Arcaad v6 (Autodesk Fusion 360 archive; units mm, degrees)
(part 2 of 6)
sketch "Sketch14" plane through (0, -337.8868, -90.9298) normal (0, 0.9656, 0.2599) x axis (1, 0, 0)
  line L1 (212, -233.7285) -> (224, -233.7285)
  line L2 (212, -143.475) -> (212, -233.7285)
  line L3 (-288, -143.475) -> (212, -143.475)
  line L4 (-288, -233.7285) -> (-288, -143.475)
  line L5 (-300, -233.7285) -> (-288, -233.7285)
  line L6 (-300, -293.7285) -> (-300, -233.7285)
  line L7 (-288, -293.7285) -> (-300, -293.7285)
  line L8 (-288, -383.9821) -> (-288, -293.7285)
  line L9 (212, -383.9821) -> (-288, -383.9821)
  line L10 (212, -293.7285) -> (212, -383.9821)
  line L11 (224, -293.7285) -> (212, -293.7285)
  line L12 (224, -233.7285) -> (224, -293.7285)
  line L13 (212, -143.475) -> (-288, -143.475)
  line L14 (212, -383.9821) -> (212, -143.475)
  line L15 (-288, -383.9821) -> (212, -383.9821)
  line L16 (-288, -143.475) -> (-288, -383.9821)
  line L17 (212, -263.7285) -> (-288, -263.7285)
  line L18 (-38, -383.9821) -> (-38, -143.475)
  line L19 (87, -383.9821) -> (87, -143.475)
  line L20 (-163, -143.475) -> (-163, -383.9821)
  point P11 (212, -383.9821)
  point P16 (212, -383.9821)
  point P5 (-288, -143.475)
  point P14 (-288, -143.475)
  point P18 (-288, -263.7285)
  point P19 (212, -263.7285)
  point P20 (-38, -143.475)
  point P21 (-38, -383.9821)
  horizontal L13
  vertical L14
  horizontal L15
  vertical L16
  coincident P11 P16
  coincident P5 P14
  midpoint L16 P18
  midpoint L14 P19
  midpoint L3 P20
  midpoint L9 P21
  dimension "d74" distance P18 P19 = 500
  dimension "d75" = 125 (= "( 500 / 4 ) * 1 mm")
  dimension "d76" = 125 (= "( 500 / 4 ) * 1 mm")
component_insert "Component Insert3"
joint "Assemble1" OffsetX 0 OffsetY 0 OffsetZ 0 AngleZ 0 alignAngle 0 alignOffsetX 0 alignOffsetY 0 alignOffsetZ 0
work_plane "WorkPlane1"
form "Form1"
position "Position10"
mirror_component "MirrorComponent1"
derived_instance "DerivedInstance1"
derived_instance "DerivedInstance1"
derived_instance "DerivedInstance2"
derived_instance "DerivedInstance3"
derived_instance "DerivedInstance4"
derived_instance "DerivedInstance5"
derived_instance "DerivedInstance1"
derived_instance "DerivedInstance2"
derived_instance "DerivedInstance3"
position "Position11"
combine "Combine2"
position "Position12"
sketch "Sketch15" plane through (1060.5317, -231.9707, -369.061) normal (0, 0.9656, 0.2599) x axis (1, 0, 0)
  line L1 (-848.5317, -529.8285) -> (-836.5317, -529.8285)
  line L2 (-848.5317, -439.5749) -> (-848.5317, -529.8285)
  line L3 (-1348.5317, -439.5749) -> (-848.5317, -439.5749)
  line L4 (-1348.5317, -529.8285) -> (-1348.5317, -439.5749)
  line L5 (-1360.5317, -529.8285) -> (-1348.5317, -529.8285)
  line L6 (-1360.5317, -589.8285) -> (-1360.5317, -529.8285)
  line L7 (-1348.5317, -589.8285) -> (-1360.5317, -589.8285)
  line L8 (-1348.5317, -680.0821) -> (-1348.5317, -589.8285)
  line L9 (-848.5317, -680.0821) -> (-1348.5317, -680.0821)
  line L10 (-848.5317, -589.8285) -> (-848.5317, -680.0821)
  line L11 (-836.5317, -589.8285) -> (-848.5317, -589.8285)
  line L12 (-836.5317, -529.8285) -> (-836.5317, -589.8285)
  line L13 (-1207.5033, -539.8501) -> (-1239.5601, -539.8501)
  line L14 (-1207.5033, -579.8069) -> (-1207.5033, -539.8501)
  line L15 (-1239.5601, -579.8069) -> (-1207.5033, -579.8069)
  line L16 (-1239.5601, -539.8501) -> (-1239.5601, -579.8069)
  line L17 (-989.5601, -539.8501) -> (-957.5033, -539.8501)
  line L18 (-989.5601, -579.8069) -> (-989.5601, -539.8501)
  line L19 (-957.5033, -579.8069) -> (-989.5601, -579.8069)
  line L20 (-957.5033, -539.8501) -> (-957.5033, -579.8069)
  horizontal L13
  vertical L14
  horizontal L15
  vertical L16
  horizontal L17
  vertical L18
  horizontal L19
  vertical L20
extrude "Extrude2" cut sketch "Sketch15" profile of L13 L14 L15 L16 L17 L18 L19 L20 against normal blind 12
position "Position14"
sketch "Sketch16" plane through (0, 0, 0) normal (0, 1, 0) x axis (1, 0, 0)
  line L1 (2740, 0) -> (300, 0)
  line L2 (2740, -1220) -> (2740, 0)
  line L3 (300, -1220) -> (2740, -1220)
  line L4 (300, 0) -> (300, -1220)
  point P2 (300, 0)
  point P3 (2740, 0)
  point P5 (300, -1220)
  horizontal L1
  vertical L2
  horizontal L3
  vertical L4
  dimension "d91" distance P2 P3 = 2440
  dimension "d92" distance P2 P5 = 1220
extrude "Extrude1" new body sketch "Sketch16" against normal blind 12
sketch "Sketch18" plane through (-288, 0, 0) normal (1, 0, 0) x axis (0, 0, -1)
  line L1 (-133.2097, -404.4191) -> (-134.7689, -398.6252)
  line L2 (-123.5532, -401.8204) -> (-133.2097, -404.4191)
  line L3 (-121.994, -407.6143) -> (-123.5532, -401.8204)
  line L4 (-199.2455, -428.4037) -> (-121.994, -407.6143)
  line L5 (-200.8048, -422.6098) -> (-199.2455, -428.4037)
  line L6 (-191.1483, -420.0112) -> (-200.8048, -422.6098)
  line L7 (-192.7075, -414.2173) -> (-191.1483, -420.0112)
  line L8 (-134.7689, -398.6252) -> (-192.7075, -414.2173)
  line L9 (-208.6564, -584.2019) -> (-287.6564, -584.2019)
  line L10 (-208.6564, -596.2019) -> (-208.6564, -584.2019)
  line L11 (-128.6564, -596.2019) -> (-208.6564, -596.2019)
  line L12 (-128.6564, -584.2019) -> (-128.6564, -596.2019)
  line L13 (-33.6564, -584.2019) -> (-128.6564, -584.2019)
  line L14 (-33.6564, -596.2019) -> (-33.6564, -584.2019)
  line L15 (46.3436, -596.2019) -> (-33.6564, -596.2019)
  line L16 (46.3436, -584.2019) -> (46.3436, -596.2019)
  line L17 (141.3436, -584.2019) -> (46.3436, -584.2019)
  line L18 (141.3436, -596.2019) -> (141.3436, -584.2019)
  line L19 (221.3436, -596.2019) -> (141.3436, -596.2019)
  line L20 (221.3436, -584.2019) -> (221.3436, -596.2019)
  line L21 (300.3436, -584.2019) -> (221.3436, -584.2019)
  line L22 (300.3436, -393.4667) -> (300.3436, -584.2019)
  line L23 (312.3436, -393.4667) -> (300.3436, -393.4667)
  line L24 (312.3436, -313.4667) -> (312.3436, -393.4667)
  line L25 (300.3436, -313.4667) -> (312.3436, -313.4667)
  line L26 (300.3436, -143.4667) -> (300.3436, -313.4667)
  line L27 (312.3436, -143.4667) -> (300.3436, -143.4667)
  line L28 (312.3436, -63.4667) -> (312.3436, -143.4667)
  line L29 (300.3436, -63.4667) -> (312.3436, -63.4667)
  line L30 (300.3436, 106.5333) -> (300.3436, -63.4667)
  line L31 (312.3436, 106.5333) -> (300.3436, 106.5333)
  line L32 (312.3436, 186.5333) -> (312.3436, 106.5333)
  line L33 (300.3436, 186.5333) -> (312.3436, 186.5333)
  line L34 (300.3436, 377.2686) -> (300.3436, 186.5333)
  line L35 (207.9218, 377.2686) -> (300.3436, 377.2686)
  line L36 (207.9218, 389.2686) -> (207.9218, 377.2686)
  line L37 (127.9218, 389.2686) -> (207.9218, 389.2686)
  line L38 (127.9218, 377.2686) -> (127.9218, 389.2686)
  line L39 (23.4999, 377.2686) -> (127.9218, 377.2686)
  line L40 (23.4999, 389.2686) -> (23.4999, 377.2686)
  line L41 (11.6822, 391.3524) -> (23.4999, 389.2686)
  line L42 (2.9998, 342.112) -> (11.6822, 391.3524)
  line L43 (64.0579, 331.3458) -> (2.9998, 342.112)
  line L44 (66.1417, 343.1635) -> (64.0579, 331.3458)
  line L45 (77.9594, 341.0797) -> (66.1417, 343.1635)
  line L46 (60.5946, 242.5989) -> (77.9594, 341.0797)
  line L47 (48.7769, 244.6827) -> (60.5946, 242.5989)
  line L48 (31.412, 146.2019) -> (48.7769, 244.6827)
  line L49 (43.2297, 144.1182) -> (31.412, 146.2019)
  line L50 (25.8649, 45.6374) -> (43.2297, 144.1182)
  line L51 (14.0472, 47.7212) -> (25.8649, 45.6374)
  line L52 (1.0236, -26.1394) -> (14.0472, 47.7212)
  line L53 (12.8413, -28.2232) -> (1.0236, -26.1394)
  line L54 (-13.2059, -175.9444) -> (12.8413, -28.2232)
  line L55 (-25.0236, -173.8606) -> (-13.2059, -175.9444)
  line L56 (-33.706, -223.101) -> (-25.0236, -173.8606)
  line L57 (-21.8883, -225.1847) -> (-33.706, -223.101)
  line L58 (-43.5944, -348.2857) -> (-21.8883, -225.1847)
  line L59 (-55.412, -346.2019) -> (-43.5944, -348.2857)
  line L60 (-142.5649, -369.6559) -> (-55.412, -346.2019)
  line L61 (-141.0057, -375.4498) -> (-142.5649, -369.6559)
  line L62 (-131.3492, -372.8511) -> (-141.0057, -375.4498)
  line L63 (-129.79, -378.645) -> (-131.3492, -372.8511)
  line L64 (-207.0416, -399.4344) -> (-129.79, -378.645)
  line L65 (-208.6008, -393.6405) -> (-207.0416, -399.4344)
  line L66 (-198.9443, -391.0418) -> (-208.6008, -393.6405)
  line L67 (-200.5035, -385.248) -> (-198.9443, -391.0418)
  line L68 (-287.6564, -408.7019) -> (-200.5035, -385.248)
  line L69 (-287.6564, -477.4519) -> (-287.6564, -408.7019)
  line L70 (-299.6564, -477.4519) -> (-287.6564, -477.4519)
  line L71 (-299.6564, -527.4519) -> (-299.6564, -477.4519)
  line L72 (-287.6564, -527.4519) -> (-299.6564, -527.4519)
  line L73 (-287.6564, -584.2019) -> (-287.6564, -527.4519)
  line L74 (240, -320) -> (-30, -320)
  line L75 (240, -332) -> (240, -320)
  line L76 (-30, -332) -> (240, -332)
  line L77 (-30, -320) -> (-30, -332)
  line L78 (105, -332) -> (105, -320)
  line L79 (240, -326) -> (-30, -326)
  line L80 (37.5, -332) -> (37.5, -320)
  line L81 (172.5, -332) -> (172.5, -320)
  line L82 (17.5, -320) -> (37.5, -320)
  line L83 (17.5, -332) -> (17.5, -320)
  line L84 (37.5, -332) -> (17.5, -332)
  line L85 (37.5, -320) -> (37.5, -332)
  line L86 (57.5, -320) -> (37.5, -320)
  line L87 (57.5, -332) -> (57.5, -320)
  line L88 (37.5, -332) -> (57.5, -332)
  line L89 (37.5, -320) -> (37.5, -332)
  line L90 (67.5, -320) -> (37.5, -320)
  line L91 (67.5, -332) -> (67.5, -320)
  line L92 (37.5, -332) -> (67.5, -332)
  line L93 (37.5, -320) -> (37.5, -332)
  line L94 (7.5, -320) -> (37.5, -320)
  line L95 (7.5, -332) -> (7.5, -320)
  line L96 (37.5, -332) -> (7.5, -332)
  line L97 (37.5, -320) -> (37.5, -332)
  line L98 (202.5, -332) -> (202.5, -320)
  line L99 (172.5, -332) -> (202.5, -332)
  line L100 (202.5, -320) -> (172.5, -320)
  line L101 (172.5, -320) -> (172.5, -332)
  line L102 (152.5, -332) -> (152.5, -320)
  line L103 (192.5, -332) -> (192.5, -320)
  line L104 (172.5, -320) -> (172.5, -332)
  line L105 (172.5, -332) -> (142.5, -332)
  line L106 (142.5, -320) -> (172.5, -320)
  line L107 (142.5, -332) -> (142.5, -320)
  point P79 (105, -320)
  point P80 (105, -332)
  point P81 (-30, -326)
  point P82 (240, -326)
  point P91 (57.5, -332)
  point P83 (37.5, -320)
  point P102 (172.5, -320)
  point P87 (17.5, -320)
  point P105 (192.5, -320)
  point P88 (17.5, -332)
  point P106 (192.5, -332)
  point P90 (57.5, -320)
  point P103 (152.5, -320)
  point P104 (152.5, -332)
  point P93 (67.5, -320)
  point P109 (142.5, -320)
  point P94 (67.5, -332)
  point P108 (142.5, -332)
  point P95 (37.5, -332)
  point P107 (172.5, -332)
  point P96 (7.5, -320)
  point P99 (202.5, -320)
  point P97 (7.5, -332)
  point P100 (202.5, -332)
  point P98 (37.5, -332)
  point P101 (172.5, -332)
  point P76 (240, -320)
  point P77 (240, -332)
  point P78 (-30, -332)
  horizontal L74
  vertical L75
  horizontal L76
  vertical L77
  midpoint L74 P79
  midpoint L76 P80
  midpoint L77 P81
  midpoint L75 P82
  horizontal L82
  vertical L83
  horizontal L84
  vertical L85
  horizontal L86
  vertical L87
  horizontal L88
  vertical L89
  coincident L76 P91
  horizontal L90
  vertical L91
  horizontal L92
  vertical L93
  horizontal L94
  vertical L95
  horizontal L96
  vertical L97
  symmetric L78 P83 P102
  symmetric L78 P87 P105
  symmetric L78 P88 P106
  symmetric L78 P90 P103
  symmetric L78 P91 P104
  symmetric L78 P93 P109
  symmetric L78 P94 P108
  symmetric L78 P95 P107
  symmetric L78 P96 P99
  symmetric L78 P97 P100
  symmetric L78 P98 P101
  dimension "d240" distance P76 P77 = 12
  dimension "d241" distance P77 P78 = 270
  dimension "d242" = 67.5 (= "( 270 / 4 ) * 1 mm")
  dimension "d243" = 67.5 (= "( 270 / 4 ) * 1 mm")
  dimension "d244" distance P83 P87 = 20
  dimension "d245" distance P83 P90 = 20
  dimension "d246" distance P83 P93 = 30
  dimension "d247" distance P83 P96 = 30
extrude "Extrude1" new body sketch "Sketch18" profile of L74 L75 L76 L77 L78 L79 L80 L81 L82 L83 L84 L85 L86 L87 L88 L89 L90 L91 L92 L93 L94 L95 L96 L97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 to an object
extrude "Extrude2" add sketch "Sketch18" profile of L74 L76 L79 L80 L81 L82 L83 L84 L85 L86 L87 L88 L89 L90 L91 L92 L93 L94 L95 L96 L97 L98 L99 L100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 to an object
work_plane "WorkPlane3" sketch "Sketch18"
mirror_component "MirrorComponent3"
derived_instance "DerivedInstance3"
combine "Combine1"
combine "Combine3"
combine "Combine3"
joint "Assemble2" alignAngle 0 alignOffsetX -925 alignOffsetY 275 alignOffsetZ 0
joint "Assemble3" alignAngle 0 alignOffsetX -375 alignOffsetY 100 alignOffsetZ 0
joint "Assemble4" alignAngle 0 alignOffsetX -925 alignOffsetY -175 alignOffsetZ 0
joint "Assemble5" alignAngle 0 alignOffsetX -925 alignOffsetY -450 alignOffsetZ 0
joint "Assemble6" alignAngle 0 alignOffsetX -350 alignOffsetY -500 alignOffsetZ -12
component_from_bodies "Body->Comp1"
ground "Ground1"
position "Position15"
work_plane "WorkPlane2" AlongDistance 400
mirror_component "MirrorComponent2"
derived_instance "DerivedInstance2"
joint "Assemble7" alignAngle 15 alignOffsetX 600 alignOffsetY -400 alignOffsetZ -12
joint "Assemble8" alignAngle 270 alignOffsetX -50 alignOffsetY -575 alignOffsetZ -12
position "Position16"
joint "Assemble9" alignAngle -90 alignOffsetX 450 alignOffsetY 200 alignOffsetZ 0
ground "Ground2"
ground "Ground3"
joint "Assemble10" alignAngle 0 alignOffsetX 575 alignOffsetY -275 alignOffsetZ 0
position "Position17"
sketch "Sketch17" plane through (0, 0, 0) normal (0, 1, 0) x axis (1, 0, 0)
  line L1 (2740, -1300) -> (300, -1300)
  line L2 (2740, -2520) -> (2740, -1300)
  line L3 (300, -2520) -> (2740, -2520)
  line L4 (300, -1300) -> (300, -2520)
  point P2 (300, -1300)
  point P3 (2740, -1300)
  point P5 (300, -2520)
  horizontal L1
  vertical L2
  horizontal L3
  vertical L4
  dimension "d204" distance P2 P3 = 2440
  dimension "d205" distance P2 P5 = 1220
extrude "Extrude2" new body sketch "Sketch17" against normal blind 12
component_from_bodies "Body->Comp2"
ground "Ground4"
joint "Assemble11" alignAngle 0 alignOffsetX -950 alignOffsetY 450 alignOffsetZ 0
joint "Assemble12" alignAngle 0 alignOffsetX -950 alignOffsetY 200 alignOffsetZ -12
position "Position18"
joint "Assemble13" alignAngle 0 alignOffsetX -950 alignOffsetY -50 alignOffsetZ 0
sketch "Sketch19" plane through (0, 0, 0) normal (0, 1, 0) x axis (-1, 0, 0)
  line L1 (-2740, 2520) -> (-300, 2520)
  line L2 (-2740, 1300) -> (-2740, 2520)
  line L3 (-300, 1300) -> (-2740, 1300)
  line L4 (-300, 2520) -> (-300, 1300)
  line L5 (-2610.2394, 933.8303) -> (-2610.2459, 927.8302)
  line L6 (-2550.2394, 933.7651) -> (-2610.2394, 933.8303)
  line L7 (-2550.2459, 927.7651) -> (-2550.2394, 933.7651)
  line L8 (-2560.2459, 927.776) -> (-2550.2459, 927.7651)
  line L9 (-2560.2524, 921.776) -> (-2560.2459, 927.776)
  line L10 (-2600.2524, 921.8194) -> (-2560.2524, 921.776)
  line L11 (-2600.2459, 927.8194) -> (-2600.2524, 921.8194)
  line L12 (-2610.2459, 927.8302) -> (-2600.2459, 927.8194)
  line L13 (-2475.2394, 933.6837) -> (-2475.246, 927.6837)
  line L14 (-2415.2395, 933.6185) -> (-2475.2394, 933.6837)
  line L15 (-2415.246, 927.6185) -> (-2415.2395, 933.6185)
  line L16 (-2425.246, 927.6294) -> (-2415.246, 927.6185)
  line L17 (-2425.2525, 921.6294) -> (-2425.246, 927.6294)
  line L18 (-2465.2525, 921.6728) -> (-2425.2525, 921.6294)
  line L19 (-2465.246, 927.6728) -> (-2465.2525, 921.6728)
  line L20 (-2475.246, 927.6837) -> (-2465.246, 927.6728)
  line L21 (-2563.7962, 1197.9819) -> (-2563.8092, 1185.9819)
  line L22 (-2613.7961, 1198.0362) -> (-2563.7962, 1197.9819)
  line L23 (-2613.8092, 1186.0362) -> (-2613.7961, 1198.0362)
  line L24 (-2707.8091, 1186.1383) -> (-2613.8092, 1186.0362)
  line L25 (-2708.0325, 980.4031) -> (-2707.8091, 1186.1383)
  line L26 (-2720.0325, 980.4161) -> (-2708.0325, 980.4031)
  line L27 (-2720.0868, 930.4162) -> (-2720.0325, 980.4161)
  line L28 (-2708.0868, 930.4031) -> (-2720.0868, 930.4162)
  line L29 (-2708.3039, 730.4033) -> (-2708.0868, 930.4031)
  line L30 (-2720.3039, 730.4163) -> (-2708.3039, 730.4033)
  line L31 (-2720.3582, 680.4163) -> (-2720.3039, 730.4163)
  line L32 (-2708.3582, 680.4033) -> (-2720.3582, 680.4163)
  line L33 (-2708.5753, 480.4034) -> (-2708.3582, 680.4033)
  line L34 (-2720.5753, 480.4164) -> (-2708.5753, 480.4034)
  line L35 (-2720.6296, 430.4165) -> (-2720.5753, 480.4164)
  line L36 (-2708.6296, 430.4034) -> (-2720.6296, 430.4165)
  line L37 (-2708.8529, 224.6683) -> (-2708.6296, 430.4034)
  line L38 (-2601.4312, 224.5517) -> (-2708.8529, 224.6683)
  line L39 (-2601.4442, 212.5517) -> (-2601.4312, 224.5517)
  line L40 (-2551.4442, 212.4974) -> (-2601.4442, 212.5517)
  line L41 (-2551.4312, 224.4974) -> (-2551.4442, 212.4974)
  line L42 (-2432.0094, 224.3677) -> (-2551.4312, 224.4974)
  line L43 (-2432.0224, 212.3677) -> (-2432.0094, 224.3677)
  line L44 (-2420.207, 210.2711) -> (-2432.0224, 212.3677)
  line L45 (-2411.4712, 259.5021) -> (-2420.207, 210.2711)
  line L46 (-2472.5175, 270.3345) -> (-2411.4712, 259.5021)
  line L47 (-2474.6141, 258.5191) -> (-2472.5175, 270.3345)
  line L48 (-2486.4295, 260.6157) -> (-2474.6141, 258.5191)
  line L49 (-2464.5899, 383.6931) -> (-2486.4295, 260.6157)
  line L50 (-2452.7745, 381.5964) -> (-2464.5899, 383.6931)
  line L51 (-2444.0386, 430.8274) -> (-2452.7745, 381.5964)
  line L52 (-2455.854, 432.924) -> (-2444.0386, 430.8274)
  line L53 (-2429.6464, 580.6168) -> (-2455.854, 432.924)
  line L54 (-2417.831, 578.5202) -> (-2429.6464, 580.6168)
  line L55 (-2409.0952, 627.7511) -> (-2417.831, 578.5202)
  line L56 (-2420.9106, 629.8477) -> (-2409.0952, 627.7511)
  line L57 (-2394.703, 777.5405) -> (-2420.9106, 629.8477)
  line L58 (-2382.8876, 775.4439) -> (-2394.703, 777.5405)
  line L59 (-2374.1517, 824.6748) -> (-2382.8876, 775.4439)
  line L60 (-2385.9671, 826.7714) -> (-2374.1517, 824.6748)
  line L61 (-2364.1275, 949.8488) -> (-2385.9671, 826.7714)
  line L62 (-2352.3121, 947.7522) -> (-2364.1275, 949.8488)
  line L63 (-2265.1338, 971.1115) -> (-2352.3121, 947.7522)
  line L64 (-2266.6867, 976.9071) -> (-2265.1338, 971.1115)
  line L65 (-2276.346, 974.3189) -> (-2266.6867, 976.9071)
  line L66 (-2277.8989, 980.1144) -> (-2276.346, 974.3189)
  line L67 (-2200.6248, 1000.82) -> (-2277.8989, 980.1144)
  line L68 (-2199.0719, 995.0244) -> (-2200.6248, 1000.82)
  line L69 (-2208.7312, 992.4362) -> (-2199.0719, 995.0244)
  line L70 (-2207.1783, 986.6407) -> (-2208.7312, 992.4362)
  line L71 (-2120, 1010) -> (-2207.1783, 986.6407)
  line L72 (-2119.9254, 1078.75) -> (-2120, 1010)
  line L73 (-2107.9254, 1078.7369) -> (-2119.9254, 1078.75)
  line L74 (-2107.8711, 1128.7369) -> (-2107.9254, 1078.7369)
  line L75 (-2119.8711, 1128.7499) -> (-2107.8711, 1128.7369)
  line L76 (-2119.8095, 1185.4999) -> (-2119.8711, 1128.7499)
  line L77 (-2213.8094, 1185.6019) -> (-2119.8095, 1185.4999)
  line L78 (-2213.7964, 1197.6019) -> (-2213.8094, 1185.6019)
  line L79 (-2263.7964, 1197.6562) -> (-2213.7964, 1197.6019)
  line L80 (-2263.8094, 1185.6562) -> (-2263.7964, 1197.6562)
  line L81 (-2388.8093, 1185.7919) -> (-2263.8094, 1185.6562)
  line L82 (-2388.7963, 1197.7919) -> (-2388.8093, 1185.7919)
  line L83 (-2438.7963, 1197.8462) -> (-2388.7963, 1197.7919)
  line L84 (-2438.8093, 1185.8462) -> (-2438.7963, 1197.8462)
  line L85 (-2563.8092, 1185.9819) -> (-2438.8093, 1185.8462)
  line L86 (-2284.1105, 1003.2967) -> (-2274.4513, 1005.8848)
  line L87 (-2285.6635, 1009.0922) -> (-2284.1105, 1003.2967)
  line L88 (-2208.3894, 1029.7977) -> (-2285.6635, 1009.0922)
  line L89 (-2206.8365, 1024.0022) -> (-2208.3894, 1029.7977)
  line L90 (-2216.4957, 1021.414) -> (-2206.8365, 1024.0022)
  line L91 (-2214.9428, 1015.6184) -> (-2216.4957, 1021.414)
  line L92 (-2272.8984, 1000.0893) -> (-2214.9428, 1015.6184)
  line L93 (-2274.4513, 1005.8848) -> (-2272.8984, 1000.0893)
  line L94 (-1970, 650) -> (-2190, 650)
  line L95 (-1970, 170) -> (-1970, 650)
  line L96 (-2190, 170) -> (-1970, 170)
  line L97 (-2190, 650) -> (-2190, 170)
  line L98 (-1980, 747.9677) -> (-1900, 747.9677)
  line L99 (-1980, 753.9677) -> (-1980, 747.9677)
  line L100 (-1965, 753.9677) -> (-1980, 753.9677)
  line L101 (-1965, 759.9677) -> (-1965, 753.9677)
  line L102 (-2055, 759.9677) -> (-1965, 759.9677)
  line L103 (-2055, 753.9677) -> (-2055, 759.9677)
  line L104 (-2040, 753.9677) -> (-2055, 753.9677)
  line L105 (-2040, 747.9677) -> (-2040, 753.9677)
  line L106 (-2120, 747.9677) -> (-2040, 747.9677)
  line L107 (-2120, 753.9677) -> (-2120, 747.9677)
  line L108 (-2105, 753.9677) -> (-2120, 753.9677)
  line L109 (-2105, 759.9677) -> (-2105, 753.9677)
  line L110 (-2195, 759.9677) -> (-2105, 759.9677)
  line L111 (-2195, 753.9677) -> (-2195, 759.9677)
  line L112 (-2180, 753.9677) -> (-2195, 753.9677)
  line L113 (-2180, 747.9677) -> (-2180, 753.9677)
  line L114 (-2260, 747.9677) -> (-2180, 747.9677)
  line L115 (-2260, 753.9677) -> (-2260, 747.9677)
  line L116 (-2245, 753.9677) -> (-2260, 753.9677)
  line L117 (-2245, 759.9677) -> (-2245, 753.9677)
  line L118 (-2342, 759.9677) -> (-2245, 759.9677)
  line L119 (-2342, 634.9677) -> (-2342, 759.9677)
  line L120 (-2336, 634.9677) -> (-2342, 634.9677)
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sketch "Sketch20" plane through (0, 0, 0) normal (0, 1, 0) x axis (-1, 0, 0)
  line L1 (-856.772, 135) -> (-851.228, 135)
  line L2 (-856.772, 29) -> (-856.772, 135)
  line L3 (-780, 29) -> (-856.772, 29)
  line L4 (-780.0022, 35) -> (-780, 29)
  line L5 (-795.0022, 35) -> (-780.0022, 35)
  line L6 (-795.0045, 41) -> (-795.0022, 35)
  line L7 (-715.0045, 41) -> (-795.0045, 41)
  line L8 (-715.0022, 35) -> (-715.0045, 41)
  line L9 (-730.0022, 35) -> (-715.0022, 35)
  line L10 (-730.0022, 29) -> (-730.0022, 35)
  line L11 (-620, 29) -> (-730.0022, 29)
  line L12 (-620, 35) -> (-620, 29)
  line L13 (-635.0022, 35) -> (-620, 35)
  line L14 (-635.0045, 41) -> (-635.0022, 35)
  line L15 (-555.0045, 41) -> (-635.0045, 41)
  line L16 (-555.0022, 35) -> (-555.0045, 41)
  line L17 (-570.0022, 35) -> (-555.0022, 35)
  line L18 (-570.0022, 29) -> (-570.0022, 35)
  line L19 (-460, 29) -> (-570.0022, 29)
  line L20 (-460, 35) -> (-460, 29)
  line L21 (-475.0022, 35) -> (-460, 35)
  line L22 (-475.0045, 41) -> (-475.0022, 35)
  line L23 (-395.0045, 41) -> (-475.0045, 41)
  line L24 (-395.0022, 35) -> (-395.0045, 41)
  line L25 (-410.0022, 35) -> (-395.0022, 35)
  line L26 (-410.0022, 29) -> (-410.0022, 35)
  line L27 (-333.228, 29) -> (-410.0022, 29)
  line L28 (-333.228, 135) -> (-333.228, 29)
  line L29 (-339.228, 135) -> (-333.228, 135)
  line L30 (-339.228, 120) -> (-339.228, 135)
  line L31 (-345.228, 120) -> (-339.228, 120)
  line L32 (-345.228, 200) -> (-345.228, 120)
  line L33 (-339.228, 200) -> (-345.228, 200)
  line L34 (-339.228, 185) -> (-339.228, 200)
  line L35 (-333.228, 185) -> (-339.228, 185)
  line L36 (-333.228, 310) -> (-333.228, 185)
  line L37 (-339.228, 310) -> (-333.228, 310)
  line L38 (-339.228, 295) -> (-339.228, 310)
  line L39 (-345.228, 295) -> (-339.228, 295)
  line L40 (-345.228, 375) -> (-345.228, 295)
  line L41 (-339.228, 375) -> (-345.228, 375)
  line L42 (-339.228, 360) -> (-339.228, 375)
  line L43 (-333.228, 360) -> (-339.228, 360)
  line L44 (-333.228, 485) -> (-333.228, 360)
  line L45 (-339.228, 485) -> (-333.228, 485)
  line L46 (-339.228, 470) -> (-339.228, 485)
  line L47 (-345.228, 470) -> (-339.228, 470)
  line L48 (-345.228, 550) -> (-345.228, 470)
  line L49 (-339.228, 550) -> (-345.228, 550)
  line L50 (-339.228, 535) -> (-339.228, 550)
  line L51 (-333.228, 535) -> (-339.228, 535)
  line L52 (-333.228, 641) -> (-333.228, 535)
  line L53 (-410.228, 641) -> (-333.228, 641)
  line L54 (-410.228, 635) -> (-410.228, 641)
  line L55 (-395.2258, 635) -> (-410.228, 635)
  line L56 (-395.2236, 629) -> (-395.2258, 635)
  line L57 (-475.2236, 629) -> (-395.2236, 629)
  line L58 (-475.2258, 635) -> (-475.2236, 629)
  line L59 (-460.2258, 635) -> (-475.2258, 635)
  line L60 (-460.2258, 641) -> (-460.2258, 635)
  line L61 (-570.228, 641) -> (-460.2258, 641)
  line L62 (-570.228, 640.9907) -> (-570.228, 641)
  line L63 (-570.2258, 635) -> (-570.228, 640.9907)
  line L64 (-555.2258, 635) -> (-570.2258, 635)
  line L65 (-555.2236, 629) -> (-555.2258, 635)
  line L66 (-635.2236, 629) -> (-555.2236, 629)
  line L67 (-635.2258, 635) -> (-635.2236, 629)
  line L68 (-620.2258, 635) -> (-635.2258, 635)
  line L69 (-620.228, 640.9907) -> (-620.2258, 635)
  line L70 (-620.228, 641) -> (-620.228, 640.9907)
  line L71 (-730.228, 641) -> (-620.228, 641)
  line L72 (-730.228, 635) -> (-730.228, 641)
  line L73 (-715.2258, 635) -> (-730.228, 635)
  line L74 (-715.2236, 629) -> (-715.2258, 635)
  line L75 (-795.2236, 629) -> (-715.2236, 629)
  line L76 (-795.2258, 635) -> (-795.2236, 629)
  line L77 (-780.2258, 635) -> (-795.2258, 635)
  line L78 (-780.2258, 641) -> (-780.2258, 635)
  line L79 (-856.772, 641) -> (-780.2258, 641)
  line L80 (-856.772, 535) -> (-856.772, 641)
  line L81 (-851.228, 535) -> (-856.772, 535)
  line L82 (-851.228, 550) -> (-851.228, 535)
  line L83 (-845.228, 550) -> (-851.228, 550)
  line L84 (-845.228, 470) -> (-845.228, 550)
  line L85 (-851.228, 470) -> (-845.228, 470)
  line L86 (-851.228, 485) -> (-851.228, 470)
  line L87 (-856.772, 485) -> (-851.228, 485)
  line L88 (-856.772, 360) -> (-856.772, 485)
  line L89 (-851.228, 360) -> (-856.772, 360)
  line L90 (-851.228, 375) -> (-851.228, 360)
  line L91 (-845.228, 375) -> (-851.228, 375)
  line L92 (-845.228, 295) -> (-845.228, 375)
  line L93 (-851.228, 295) -> (-845.228, 295)
  line L94 (-851.228, 310) -> (-851.228, 295)
  line L95 (-856.772, 310) -> (-851.228, 310)
  line L96 (-856.772, 185) -> (-856.772, 310)
  line L97 (-851.228, 185) -> (-856.772, 185)
  line L98 (-851.228, 200) -> (-851.228, 185)
  line L99 (-845.228, 200) -> (-851.228, 200)
  line L100 (-845.228, 120) -> (-845.228, 200)
  line L101 (-851.228, 120) -> (-845.228, 120)
  line L102 (-851.228, 135) -> (-851.228, 120)
  line L103 (-1104.9955, 990.7353) -> (-1104.9955, 1002.7353)
  line L104 (-1024.9955, 990.7353) -> (-1104.9955, 990.7353)
  line L105 (-1024.9955, 1002.7353) -> (-1024.9955, 990.7353)
  line L106 (-944.9955, 1002.7353) -> (-1024.9955, 1002.7353)
  line L107 (-944.9955, 990.7353) -> (-944.9955, 1002.7353)
  line L108 (-883, 990.7353) -> (-944.9955, 990.7353)
  line L109 (-883, 785) -> (-883, 990.7353)
  line L110 (-889, 785) -> (-883, 785)
  line L111 (-889, 800) -> (-889, 785)
  line L112 (-895, 800) -> (-889, 800)
  line L113 (-895, 720) -> (-895, 800)
  line L114 (-889, 720) -> (-895, 720)
  line L115 (-889, 735) -> (-889, 720)
  line L116 (-883, 735) -> (-889, 735)
  line L117 (-883, 535) -> (-883, 735)
  line L118 (-889, 535) -> (-883, 535)
  line L119 (-889, 550) -> (-889, 535)
  line L120 (-895, 550) -> (-889, 550)
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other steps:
derived_base_feature "Derived Base Feature1"
derived_base_feature "Derived Base Feature1"
derived_base_feature "Derived Base Feature1"
derived_base_feature "Derived Base Feature1"
derived_base_feature "Derived Base Feature1"
derived_base_feature "Derived Base Feature1"
derived_base_feature "Derived Base Feature1"
derived_base_feature "Derived Base Feature1"
derived_base_feature "Derived Base Feature1"
derived_base_feature "Derived Base Feature1"
create_component "CreateComponent1"
create_component "CreateComponent2"
create_component "CreateComponent3"
create_component "CreateComponent4"
create_component "CreateComponent5"
create_component "CreateComponent6"
create_component "CreateComponent7"
create_component "CreateComponent8"
create_component "CreateComponent9"
create_component "CreateComponent10"
joint_origin "JointOrigin1" sketch "Sketch14" OffsetX 0 OffsetY 0 OffsetZ 0 AngleZ 0
create_component "CreateComponent11"
create_component "CreateComponent12"
create_component "CreateComponent13"
create_component "CreateComponent14"
create_component "CreateComponent15"
create_component "CreateComponent16"
joint_origin "JointOrigin1" OffsetX 0 OffsetY 0 OffsetZ 0 AngleZ 0
joint_origin "JointOrigin2" OffsetX 0 OffsetY 0 OffsetZ 0 AngleZ 0
joint_origin "JointOrigin1" OffsetX 0 OffsetY 0 OffsetZ 0 AngleZ 0
joint_origin "JointOrigin3" OffsetX 0 OffsetY 0 OffsetZ 0 AngleZ 0
joint_origin "JointOrigin1" OffsetX 0 OffsetY 0 OffsetZ 0 AngleZ 0
joint_origin "JointOrigin4" OffsetX 0 OffsetY 0 OffsetZ 0 AngleZ 0
joint_origin "JointOrigin2" OffsetX 0 OffsetY 0 OffsetZ 0 AngleZ 0
joint_origin "JointOrigin5" OffsetX 0 OffsetY 0 OffsetZ 0 AngleZ 0
joint_origin "JointOrigin1" OffsetX 0 OffsetY 0 OffsetZ 0 AngleZ 0
joint_origin "JointOrigin6" OffsetX 0 OffsetY 0 OffsetZ 0 AngleZ 0
create_component "CreateComponent17"
base_feature "Base Feature1"
remove_body "RemoveBody1"
create_component "CreateComponent18"
derived_base_feature "Derived Base Feature1"
joint_origin "JointOrigin1" OffsetX 0 OffsetY 0 OffsetZ 0 AngleZ 0
joint_origin "JointOrigin1" OffsetX 0 OffsetY 0 OffsetZ 0 AngleZ 0
joint_origin "JointOrigin1" OffsetX 0 OffsetY 0 OffsetZ 0 AngleZ 0
joint_origin "JointOrigin2" OffsetX 0 OffsetY 0 OffsetZ 0 AngleZ 0
joint_origin "JointOrigin1" OffsetX 0 OffsetY 0 OffsetZ 0 AngleZ 0
joint_origin "JointOrigin3" OffsetX 0 OffsetY 0 OffsetZ 0 AngleZ 0
joint_origin "JointOrigin1" OffsetX 0 OffsetY 0 OffsetZ 0 AngleZ 0
joint_origin "JointOrigin4" OffsetX 0 OffsetY 0 OffsetZ 0 AngleZ 0
create_component "CreateComponent19"
base_feature "Base Feature1" OffsetX 0 OffsetY 0 OffsetZ 0 AngleZ 0
remove_body "RemoveBody2"
joint_origin "JointOrigin1" OffsetX 0 OffsetY 0 OffsetZ 0 AngleZ 0
joint_origin "JointOrigin1" OffsetX 0 OffsetY 0 OffsetZ 0 AngleZ 0
joint_origin "JointOrigin2" OffsetX 0 OffsetY 0 OffsetZ 0 AngleZ 0
joint_origin "JointOrigin3" OffsetX 0 OffsetY 0 OffsetZ 0 AngleZ 0
create_component "CreateComponent20"
create_component "CreateComponent21"
create_component "CreateComponent22"
remove_body "RemoveBody1"
joint_origin "JointOrigin1" OffsetX 0 OffsetY 0 OffsetZ 0 AngleZ 0
joint_origin "JointOrigin4" OffsetX 0 OffsetY 0 OffsetZ 0 AngleZ 0
create_component "CreateComponent23"
create_component "CreateComponent24"
create_component "CreateComponent25"

design "Micro Switch de Alavanca"
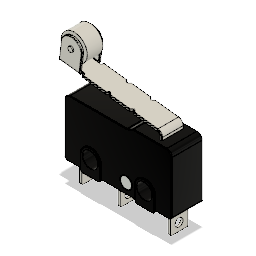
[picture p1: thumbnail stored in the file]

design "Arcade_Box" references "Joystick assembly", "Untitled"
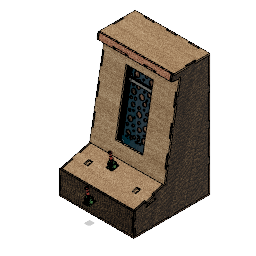
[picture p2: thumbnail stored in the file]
sketch "Sketch1" plane through (0, 0, 0) normal (0, 0, 1) x axis (1, 0, 0)
  line L1 (-300, 350) -> (300, 350)
  line L2 (-300, -350) -> (-300, 350)
  line L3 (300, -350) -> (-300, -350)
  line L4 (300, 350) -> (300, -350)
  line L5 (-300, -350) -> (300, 350)
  line L6 (300, -350) -> (-300, 350)
  line L7 (150, 300) -> (-150, 300)
  line L8 (150, -300) -> (150, 300)
  line L9 (-150, -300) -> (150, -300)
  line L10 (-150, 300) -> (-150, -300)
  line L11 (150, -300) -> (-150, 300)
  line L12 (-150, -300) -> (150, 300)
  line L13 (-110, 245) -> (110, 245)
  line L14 (-110, -245) -> (-110, 245)
  line L15 (110, -245) -> (-110, -245)
  line L16 (110, 245) -> (110, -245)
  line L17 (-110, -245) -> (110, 245)
  line L18 (110, -245) -> (-110, 245)
  line L19 (288, -338) -> (-288, -338)
  line L20 (288, 338) -> (288, -338)
  line L21 (-288, 338) -> (288, 338)
  line L22 (-288, -338) -> (-288, 338)
  line L23 (294, -344) -> (-294, -344)
  line L24 (294, 344) -> (294, -344)
  line L25 (-294, 344) -> (294, 344)
  line L26 (-294, -344) -> (-294, 344)
  line L27 (0, -350) -> (0, 350)
  line L28 (300, 0) -> (-300, 0)
  line L29 (300, -25) -> (-300, -25)
  line L30 (300, -50) -> (-300, -50)
  line L31 (300, 25) -> (-300, 25)
  line L32 (300, 50) -> (-300, 50)
  line L33 (300, -150) -> (-300, -150)
  line L34 (300, -175) -> (-300, -175)
  line L35 (300, -200) -> (-300, -200)
  line L36 (300, -225) -> (-300, -225)
  line L37 (300, -250) -> (-300, -250)
  line L38 (300, 250) -> (-300, 250)
  line L39 (300, 225) -> (-300, 225)
  line L40 (300, 200) -> (-300, 200)
  line L41 (300, 175) -> (-300, 175)
  line L42 (300, 150) -> (-300, 150)
  line L43 (-50, -350) -> (-50, 350)
  line L44 (50, -350) -> (50, 350)
  line L45 (25, -350) -> (25, 350)
  line L46 (-25, -350) -> (-25, 350)
  line L47 (-150, -350) -> (-150, 350)
  line L48 (-175, -350) -> (-175, 350)
  line L49 (-100, -350) -> (-100, 350)
  line L50 (-75, -350) -> (-75, 350)
  line L51 (100, -350) -> (100, 350)
  line L52 (75, -350) -> (75, 350)
  line L53 (150, -350) -> (150, 350)
  line L54 (175, -350) -> (175, 350)
  point P6 (0, 0)
  point P1 (0, 0)
  point P11 (0, 0)
  point P16 (0, 0)
  point P25 (0, 350)
  point P26 (0, -350)
  point P27 (-300, 0)
  point P28 (300, 0)
  point P3 (-300, 350)
  point P4 (-300, -350)
  point P5 (300, -350)
  point P8 (150, 300)
  point P9 (150, -300)
  point P10 (-150, -300)
  point P13 (-110, 245)
  point P14 (-110, -245)
  point P15 (110, -245)
  perpendicular L1 L2
  parallel L1 L3
  parallel L2 L4
  horizontal L1
  coincident L5 P6
  coincident L6 P6
  coincident P1 P6
  perpendicular L7 L8
  parallel L7 L9
  parallel L8 L10
  horizontal L7
  coincident L11 P11
  coincident L12 P11
  coincident P1 P11
  perpendicular L13 L14
  parallel L13 L15
  parallel L14 L16
  horizontal L13
  coincident L17 P16
  coincident L18 P16
  coincident P6 P16
  midpoint L1 P25
  midpoint L3 P26
  midpoint L2 P27
  midpoint L4 P28
  dimension "d1" distance P3 P4 = 700
  dimension "d2" distance P4 P5 = 600
  dimension "d3" distance P8 P9 = 600
  dimension "d4" distance P9 P10 = 300
  dimension "d5" distance P13 P14 = 490
  dimension "d6" distance P14 P15 = 220
  dimension "d7" = -12
  dimension "d8" = -6
  dimension "d9" = 25 (= "( 50 / 2 ) * 1 mm")
  dimension "d10" = 50
  dimension "d11" = -25 (= "( -50 / 2 ) * 1 mm")
  dimension "d12" = -50
  dimension "d17" = 50
  dimension "d18" = -50
  dimension "d19" = -25 (= "( -50 / 2 ) * 1 mm")
  dimension "d20" = 25 (= "( 50 / 2 ) * 1 mm")
  dimension "d15" R-Pattern1-uDistance = 0
  dimension "d16" R-Pattern1-vDistance = 200
  dimension "d23" R-Pattern2-uDistance = 125
  dimension "d24" R-Pattern2-vDistance = 0
extrude "Extrude1" new body sketch "Sketch1" profile of L1 L2 L3 L4 L7 L8 L9 L10 L13 L14 L15 L16 L19 L21 L20 L22 L23 L25 L24 L26 L27 L28 L29 L30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 along normal blind 12
move "Move1"
sketch "Sketch2" plane through (0, -0.9632, -5.4629) normal (0, 0.1736, 0.9848) x axis (1, 0, 0)
  line L1 (110, -245.5646) -> (110, 244.4354)
  line L2 (-110, -245.5646) -> (110, -245.5646)
  line L3 (-110, 244.4354) -> (-110, -245.5646)
  line L4 (110, 244.4354) -> (-110, 244.4354)
  line L5 (288, 249.4354) -> (288, 149.4354)
  line L6 (294, 249.4354) -> (288, 249.4354)
  line L7 (294, 224.4354) -> (294, 249.4354)
  line L8 (300, 224.4354) -> (294, 224.4354)
  line L9 (300, 349.4354) -> (300, 224.4354)
  line L10 (150, 349.4354) -> (300, 349.4354)
  line L11 (150, 343.4354) -> (150, 349.4354)
  line L12 (175, 343.4354) -> (150, 343.4354)
  line L13 (175, 337.4354) -> (175, 343.4354)
  line L14 (75, 337.4354) -> (175, 337.4354)
  line L15 (75, 343.4354) -> (75, 337.4354)
  line L16 (100, 343.4354) -> (75, 343.4354)
  line L17 (100, 349.4354) -> (100, 343.4354)
  line L18 (-75, 349.4354) -> (100, 349.4354)
  line L19 (-75, 343.4354) -> (-75, 349.4354)
  line L20 (-50, 343.4354) -> (-75, 343.4354)
  line L21 (-50, 337.4354) -> (-50, 343.4354)
  line L22 (-175, 337.4354) -> (-50, 337.4354)
  line L23 (-175, 343.4354) -> (-175, 337.4354)
  line L24 (-150, 343.4354) -> (-175, 343.4354)
  line L25 (-150, 349.4354) -> (-150, 343.4354)
  line L26 (-300, 349.4354) -> (-150, 349.4354)
  line L27 (-300, 224.4354) -> (-300, 349.4354)
  line L28 (-294, 224.4354) -> (-300, 224.4354)
  line L29 (-294, 249.4354) -> (-294, 224.4354)
  line L30 (-288, 249.4354) -> (-294, 249.4354)
  line L31 (-288, 149.4354) -> (-288, 249.4354)
  line L32 (-294, 149.4354) -> (-288, 149.4354)
  line L33 (-294, 174.4354) -> (-294, 149.4354)
  line L34 (-300, 174.4354) -> (-294, 174.4354)
  line L35 (-300, 24.4354) -> (-300, 174.4354)
  line L36 (-294, 24.4354) -> (-300, 24.4354)
  line L37 (-294, 49.4354) -> (-294, 24.4354)
  line L38 (-288, 49.4354) -> (-294, 49.4354)
  line L39 (-288, -50.5646) -> (-288, 49.4354)
  line L40 (-294, -50.5646) -> (-288, -50.5646)
  line L41 (-294, -25.5646) -> (-294, -50.5646)
  line L42 (-300, -25.5646) -> (-294, -25.5646)
  line L43 (-300, -175.5646) -> (-300, -25.5646)
  line L44 (-294, -175.5646) -> (-300, -175.5646)
  line L45 (-294, -150.5646) -> (-294, -175.5646)
  line L46 (-288, -150.5646) -> (-294, -150.5646)
  line L47 (-288, -250.5646) -> (-288, -150.5646)
  line L48 (-294, -250.5646) -> (-288, -250.5646)
  line L49 (-294, -225.5646) -> (-294, -250.5646)
  line L50 (-300, -225.5646) -> (-294, -225.5646)
  line L51 (-300, -350.5646) -> (-300, -225.5646)
  line L52 (-150, -350.5646) -> (-300, -350.5646)
  line L53 (-150, -344.5646) -> (-150, -350.5646)
  line L54 (-175, -344.5646) -> (-150, -344.5646)
  line L55 (-175, -338.5646) -> (-175, -344.5646)
  line L56 (-75, -338.5646) -> (-175, -338.5646)
  line L57 (-75, -344.5646) -> (-75, -338.5646)
  line L58 (-100, -344.5646) -> (-75, -344.5646)
  line L59 (-100, -350.5646) -> (-100, -344.5646)
  line L60 (100, -350.5646) -> (-100, -350.5646)
  line L61 (100, -344.5646) -> (100, -350.5646)
  line L62 (75, -344.5646) -> (100, -344.5646)
  line L63 (75, -338.5646) -> (75, -344.5646)
  line L64 (175, -338.5646) -> (75, -338.5646)
  line L65 (175, -344.5646) -> (175, -338.5646)
  line L66 (150, -344.5646) -> (175, -344.5646)
  line L67 (150, -350.5646) -> (150, -344.5646)
  line L68 (300, -350.5646) -> (150, -350.5646)
  line L69 (300, -225.5646) -> (300, -350.5646)
  line L70 (294, -225.5646) -> (300, -225.5646)
  line L71 (294, -250.5646) -> (294, -225.5646)
  line L72 (288, -250.5646) -> (294, -250.5646)
  line L73 (288, -150.5646) -> (288, -250.5646)
  line L74 (294, -150.5646) -> (288, -150.5646)
  line L75 (294, -175.5646) -> (294, -150.5646)
  line L76 (300, -175.5646) -> (294, -175.5646)
  line L77 (300, -25.5646) -> (300, -175.5646)
  line L78 (294, -25.5646) -> (300, -25.5646)
  line L79 (294, -50.5646) -> (294, -25.5646)
  line L80 (288, -50.5646) -> (294, -50.5646)
  line L81 (288, 49.4354) -> (288, -50.5646)
  line L82 (294, 49.4354) -> (288, 49.4354)
  line L83 (294, 24.4354) -> (294, 49.4354)
  line L84 (300, 24.4354) -> (294, 24.4354)
  line L85 (300, 174.4354) -> (300, 24.4354)
  line L86 (288, 149.4354) -> (294, 149.4354)
  line L87 (-288, 349.4354) -> (-300, 349.4354)
  line L88 (-288, -350.5646) -> (-288, 349.4354)
  line L89 (-300, -350.5646) -> (-288, -350.5646)
  line L90 (-300, 349.4354) -> (-300, -350.5646)
  line L91 (288, 349.4354) -> (300, 349.4354)
  line L92 (288, -350.5646) -> (288, 349.4354)
  line L93 (300, -350.5646) -> (288, -350.5646)
  line L94 (300, 349.4354) -> (300, -350.5646)
  line L95 (294, 174.4354) -> (300, 174.4354)
  line L96 (294, 149.4354) -> (294, 174.4354)
  point P28 (-300, 349.4354)
  point P88 (-300, 349.4354)
  point P11 (300, 349.4354)
  point P92 (300, 349.4354)
  point P91 (-300, -350.5646)
  point P89 (-288, 349.4354)
  point P95 (300, -350.5646)
  horizontal L87
  vertical L88
  horizontal L89
  vertical L90
  coincident P28 P88
  vertical L92
  horizontal L93
  coincident P11 P92
  dimension "d27" distance P88 P91 = 700
  dimension "d28" distance P88 P89 = 12
  dimension "d29" distance P92 P95 = 700
extrude "Extrude2" new body sketch "Sketch2" profile of L5 L6 L7 L8 L9 L10 L26 L27 L28 L29 L30 L31 L32 L33 L34 L35 L36 L37 L38 L39 L40 L41 L42 L43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 against normal blind 250
sketch "Sketch3" plane through (0, -0.9632, -5.4629) normal (0, 0.1736, 0.9848) x axis (1, 0, 0)
  line L1 (110, -245.5646) -> (110, 244.4354)
  line L2 (-110, -245.5646) -> (110, -245.5646)
  line L3 (-110, 244.4354) -> (-110, -245.5646)
  line L4 (110, 244.4354) -> (-110, 244.4354)
  line L5 (288, 249.4354) -> (288, 149.4354)
  line L6 (294, 249.4354) -> (288, 249.4354)
  line L7 (294, 224.4354) -> (294, 249.4354)
  line L8 (300, 224.4354) -> (294, 224.4354)
  line L9 (300, 349.4354) -> (300, 224.4354)
  line L10 (150, 349.4354) -> (300, 349.4354)
  line L11 (150, 343.4354) -> (150, 349.4354)
  line L12 (175, 343.4354) -> (150, 343.4354)
  line L13 (175, 337.4354) -> (175, 343.4354)
  line L14 (75, 337.4354) -> (175, 337.4354)
  line L15 (75, 343.4354) -> (75, 337.4354)
  line L16 (100, 343.4354) -> (75, 343.4354)
  line L17 (100, 349.4354) -> (100, 343.4354)
  line L18 (-75, 349.4354) -> (100, 349.4354)
  line L19 (-75, 343.4354) -> (-75, 349.4354)
  line L20 (-50, 343.4354) -> (-75, 343.4354)
  line L21 (-50, 337.4354) -> (-50, 343.4354)
  line L22 (-175, 337.4354) -> (-50, 337.4354)
  line L23 (-175, 343.4354) -> (-175, 337.4354)
  line L24 (-150, 343.4354) -> (-175, 343.4354)
  line L25 (-150, 349.4354) -> (-150, 343.4354)
  line L26 (-300, 349.4354) -> (-150, 349.4354)
  line L27 (-300, 224.4354) -> (-300, 349.4354)
  line L28 (-294, 224.4354) -> (-300, 224.4354)
  line L29 (-294, 249.4354) -> (-294, 224.4354)
  line L30 (-288, 249.4354) -> (-294, 249.4354)
  line L31 (-288, 149.4354) -> (-288, 249.4354)
  line L32 (-294, 149.4354) -> (-288, 149.4354)
  line L33 (-294, 174.4354) -> (-294, 149.4354)
  line L34 (-300, 174.4354) -> (-294, 174.4354)
  line L35 (-300, 24.4354) -> (-300, 174.4354)
  line L36 (-294, 24.4354) -> (-300, 24.4354)
  line L37 (-294, 49.4354) -> (-294, 24.4354)
  line L38 (-288, 49.4354) -> (-294, 49.4354)
  line L39 (-288, -50.5646) -> (-288, 49.4354)
  line L40 (-294, -50.5646) -> (-288, -50.5646)
  line L41 (-294, -25.5646) -> (-294, -50.5646)
  line L42 (-300, -25.5646) -> (-294, -25.5646)
  line L43 (-300, -175.5646) -> (-300, -25.5646)
  line L44 (-294, -175.5646) -> (-300, -175.5646)
  line L45 (-294, -150.5646) -> (-294, -175.5646)
  line L46 (-288, -150.5646) -> (-294, -150.5646)
  line L47 (-288, -250.5646) -> (-288, -150.5646)
  line L48 (-294, -250.5646) -> (-288, -250.5646)
  line L49 (-294, -225.5646) -> (-294, -250.5646)
  line L50 (-300, -225.5646) -> (-294, -225.5646)
  line L51 (-300, -350.5646) -> (-300, -225.5646)
  line L52 (-150, -350.5646) -> (-300, -350.5646)
  line L53 (-150, -344.5646) -> (-150, -350.5646)
  line L54 (-175, -344.5646) -> (-150, -344.5646)
  line L55 (-175, -338.5646) -> (-175, -344.5646)
  line L56 (-75, -338.5646) -> (-175, -338.5646)
  line L57 (-75, -344.5646) -> (-75, -338.5646)
  line L58 (-100, -344.5646) -> (-75, -344.5646)
  line L59 (-100, -350.5646) -> (-100, -344.5646)
  line L60 (100, -350.5646) -> (-100, -350.5646)
  line L61 (100, -344.5646) -> (100, -350.5646)
  line L62 (75, -344.5646) -> (100, -344.5646)
  line L63 (75, -338.5646) -> (75, -344.5646)
  line L64 (175, -338.5646) -> (75, -338.5646)
  line L65 (175, -344.5646) -> (175, -338.5646)
  line L66 (150, -344.5646) -> (175, -344.5646)
  line L67 (150, -350.5646) -> (150, -344.5646)
  line L68 (300, -350.5646) -> (150, -350.5646)
  line L69 (300, -225.5646) -> (300, -350.5646)
  line L70 (294, -225.5646) -> (300, -225.5646)
  line L71 (294, -250.5646) -> (294, -225.5646)
  line L72 (288, -250.5646) -> (294, -250.5646)
  line L73 (288, -150.5646) -> (288, -250.5646)
  line L74 (294, -150.5646) -> (288, -150.5646)
  line L75 (294, -175.5646) -> (294, -150.5646)
  line L76 (300, -175.5646) -> (294, -175.5646)
  line L77 (300, -25.5646) -> (300, -175.5646)
  line L78 (294, -25.5646) -> (300, -25.5646)
  line L79 (294, -50.5646) -> (294, -25.5646)
  line L80 (288, -50.5646) -> (294, -50.5646)
  line L81 (288, 49.4354) -> (288, -50.5646)
  line L82 (294, 49.4354) -> (288, 49.4354)
  line L83 (294, 24.4354) -> (294, 49.4354)
  line L84 (300, 24.4354) -> (294, 24.4354)
  line L85 (300, 174.4354) -> (300, 24.4354)
  line L86 (294, 174.4354) -> (300, 174.4354)
  line L87 (294, 149.4354) -> (294, 174.4354)
  line L88 (288, 149.4354) -> (294, 149.4354)
  line L89 (-276, 261.4354) -> (-288, 261.4354)
  line L90 (-276, 137.4354) -> (-276, 261.4354)
  line L91 (-288, 137.4354) -> (-276, 137.4354)
  line L92 (-288, 61.4354) -> (-288, 137.4354)
  line L93 (-276, 61.4354) -> (-288, 61.4354)
  line L94 (-276, -62.5646) -> (-276, 61.4354)
  line L95 (-288, -62.5646) -> (-276, -62.5646)
  line L96 (-288, -138.5646) -> (-288, -62.5646)
  line L97 (-276, -138.5646) -> (-288, -138.5646)
  line L98 (-276, -262.5646) -> (-276, -138.5646)
  line L99 (-288, -262.5646) -> (-276, -262.5646)
  line L100 (-288, -338.5646) -> (-288, -262.5646)
  line L101 (-187, -338.5646) -> (-288, -338.5646)
  line L102 (-187, -326.5646) -> (-187, -338.5646)
  line L103 (-63, -326.5646) -> (-187, -326.5646)
  line L104 (-63, -338.5646) -> (-63, -326.5646)
  line L105 (63, -338.5646) -> (-63, -338.5646)
  line L106 (63, -326.5646) -> (63, -338.5646)
  line L107 (187, -326.5646) -> (63, -326.5646)
  line L108 (187, -338.5646) -> (187, -326.5646)
  line L109 (288, -338.5646) -> (187, -338.5646)
  line L110 (288, -262.5646) -> (288, -338.5646)
  line L111 (276, -262.5646) -> (288, -262.5646)
  line L112 (276, -138.5646) -> (276, -262.5646)
  line L113 (288, -138.5646) -> (276, -138.5646)
  line L114 (288, -62.5646) -> (288, -138.5646)
  line L115 (276, -62.5646) -> (288, -62.5646)
  line L116 (276, 61.4354) -> (276, -62.5646)
  line L117 (288, 61.4354) -> (276, 61.4354)
  line L118 (288, 137.4354) -> (288, 61.4354)
  line L119 (276, 137.4354) -> (288, 137.4354)
  line L120 (276, 261.4354) -> (276, 137.4354)
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  point P135 (288, 349.4354)
  coincident L10 P135
  dimension "d32" = -12
extrude "Extrude3" new body sketch "Sketch3" along normal blind 50
extrude "Extrude4" add sketch "Sketch3" to an object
